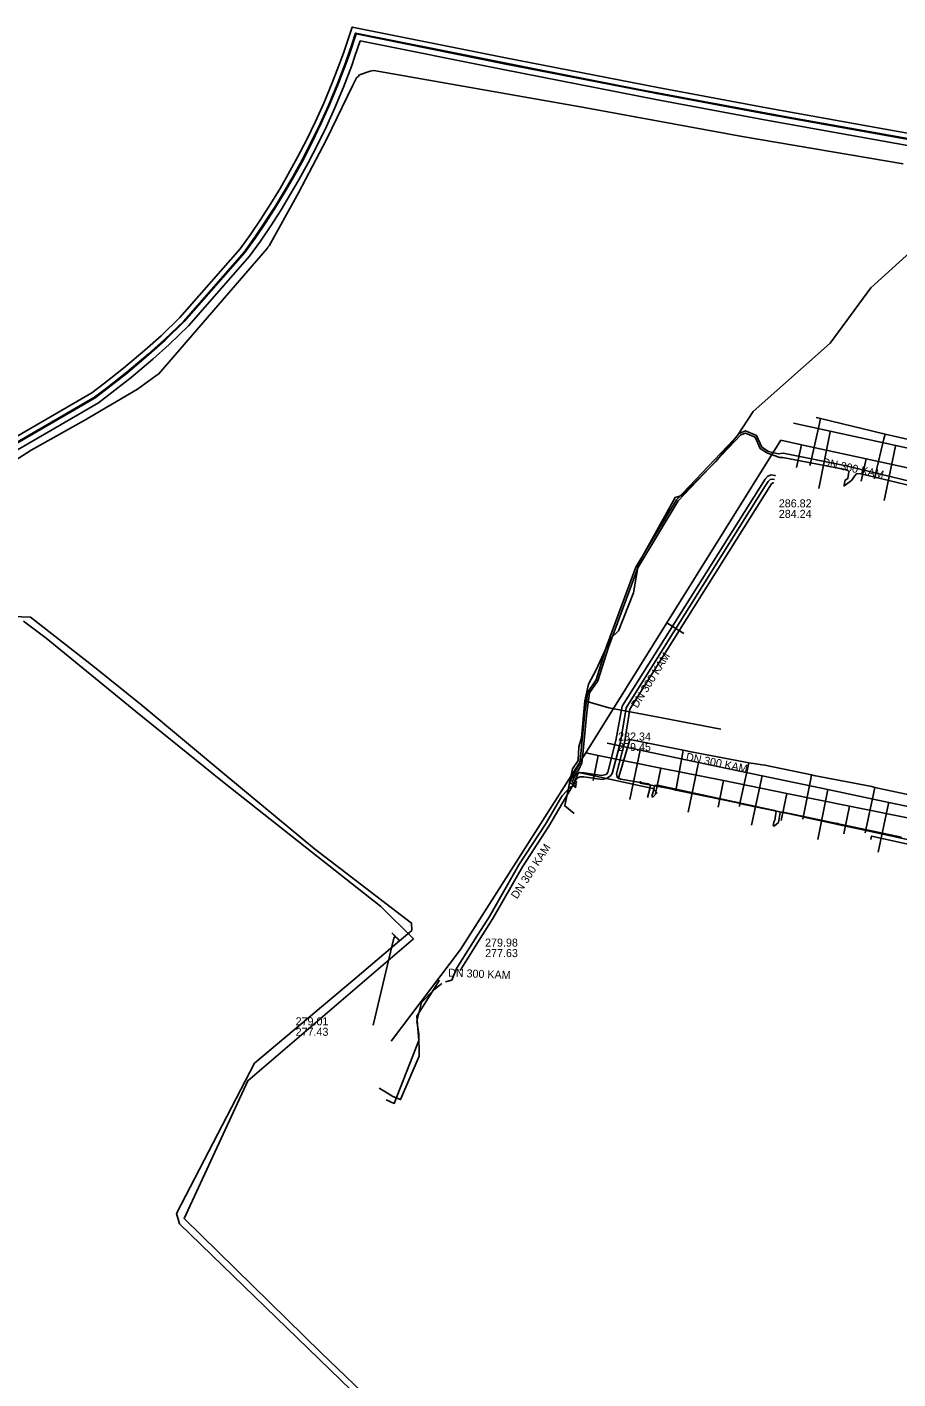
# Model space of a CAD drawing. Extents: x -598233 to -596890, y -1157848 to -1156431.
# Drawn here: x -597318.9 to -597231.9, y -1156858 to -1156722.8 of the extents above; entities that cross this region are included whole.
import ezdxf

# ---------------------------------------------------------------- set-up
doc = ezdxf.new("R2010")
doc.units = 0
for name, color, linetype in [('Vrstva 12', 7, 'Continuous'), ('Vrstva 13', 7, 'Continuous'), ('Vrstva 19', 7, 'Continuous'), ('Vrstva 25', 7, 'Continuous'), ('Vrstva 26', 7, 'Continuous'), ('Vrstva 42', 7, 'Continuous'), ('Vrstva 5', 7, 'Continuous'), ('Vrstva 55', 7, 'Continuous'), ('Vrstva 58', 7, 'Continuous'), ('Vrstva 8', 7, 'Continuous')]:
    doc.layers.add(name, color=color, linetype=linetype)

msp = doc.modelspace()

# ---------------------------------------------------------------- linework, layer by layer
at = {"layer": 'Vrstva 12'}
msp.add_lwpolyline([(-597234.61, -1156804.06), (-597234.54, -1156803.73), (-597231.51, -1156804.39), (-597202.49, -1156810.56)], dxfattribs=at)
at = {"layer": 'Vrstva 13'}
for p, q in [((-597257.65, -1156795.12), (-597258.68, -1156800.08)), ((-597251.82, -1156796.35), (-597252.86, -1156801.33)), ((-597245.48, -1156797.69), (-597246.53, -1156802.62)), ((-597238.9, -1156799.08), (-597239.92, -1156804.08)), ((-597282.25, -1156813.62), (-597282.48, -1156813.4)), ((-597282.12, -1156813.75), (-597282.25, -1156813.62)), ((-597282.12, -1156813.75), (-597281.89, -1156813.97)), ((-597281.69, -1156814.18), (-597281.89, -1156813.97))]:
    msp.add_line(p, q, dxfattribs=at)
for points in [[(-597328.73, -1156771.67), (-597318.51, -1156765.13), (-597313.2, -1156762.16), (-597307.89, -1156759.04), (-597306.04, -1156757.72), (-597305.9, -1156757.62), (-597305.77, -1156757.53), (-597294.93, -1156744.99), (-597294.84, -1156744.85), (-597294.73, -1156744.7), (-597291.79, -1156739.43), (-597288.98, -1156734.09), (-597286.37, -1156728.66), (-597286, -1156727.92), (-597285.84, -1156727.77), (-597285.69, -1156727.63), (-597284.64, -1156727.24), (-597284.46, -1156727.22), (-597284.28, -1156727.2), (-597263.27, -1156730.87), (-597247.46, -1156733.78), (-597231.39, -1156736.52)], [(-597242.34, -1156762.44), (-597238.67, -1156763.25), (-597232.12, -1156764.69), (-597225.66, -1156766.11), (-597219.64, -1156767.44), (-597211.77, -1156769.17), (-597206.62, -1156770.3), (-597200.13, -1156771.73), (-597194.02, -1156773.08), (-597187.41, -1156774.53), (-597180.74, -1156776), (-597175.41, -1156777.17)], [(-597238.67, -1156763.25), (-597238.68, -1156763.3), (-597239.82, -1156768.97)], [(-597232.12, -1156764.69), (-597232.14, -1156764.74), (-597233.28, -1156770.19)], [(-597343.01, -1156780.99), (-597342.89, -1156780.99), (-597335.69, -1156781.22), (-597318.55, -1156781.85), (-597312.16, -1156786.84), (-597307.42, -1156790.67), (-597298.96, -1156797.74), (-597290.18, -1156805), (-597286.05, -1156808.16), (-597280.5, -1156812.42), (-597280.46, -1156813.15), (-597281.69, -1156814.18), (-597286.16, -1156817.99), (-597296.2, -1156826.44), (-597303.98, -1156841.45), (-597303.68, -1156842.47), (-597277.95, -1156867.46), (-597251.84, -1156872.99), (-597228.34, -1156878.54), (-597227.3, -1156877.94), (-597211.22, -1156869.15), (-597195.71, -1156860.7), (-597186.55, -1156856.51)], [(-597181.76, -1156811.13), (-597200.74, -1156807.12), (-597207.19, -1156805.76), (-597213.61, -1156804.41), (-597219.82, -1156803.1), (-597226.76, -1156801.64), (-597232.82, -1156800.36), (-597238.9, -1156799.08), (-597245.48, -1156797.69), (-597251.82, -1156796.35), (-597257.65, -1156795.12), (-597260.62, -1156794.49), (-597260.96, -1156794.42)], [(-597232.82, -1156800.36), (-597232.84, -1156800.45), (-597233.88, -1156805.34)], [(-597282.12, -1156813.75), (-597282.21, -1156813.84), (-597282.28, -1156813.92), (-597284.35, -1156822.64)]]:
    msp.add_lwpolyline(points, dxfattribs=at)
at = {"layer": 'Vrstva 19'}
for points in [[(-597240.7, -1156766.68), (-597240.6, -1156766.3), (-597239.73, -1156762.46), (-597239.63, -1156761.99)], [(-597179.59, -1156774.8), (-597180.46, -1156774.64), (-597182.18, -1156774.29), (-597183.25, -1156774.07), (-597185.39, -1156773.51), (-597188.54, -1156772.81), (-597193.45, -1156771.7), (-597195.12, -1156771.35), (-597199.99, -1156770.31), (-597201.37, -1156770.02), (-597207.42, -1156768.72), (-597214.03, -1156767.29), (-597214.21, -1156767.25), (-597218.45, -1156766.35), (-597220.86, -1156765.93), (-597222.31, -1156765.67), (-597225.99, -1156765.16), (-597226.9, -1156764.97), (-597233.2, -1156763.53), (-597233.31, -1156763.5), (-597239.63, -1156761.99), (-597240.08, -1156761.88)], [(-597234.25, -1156768.01), (-597234.14, -1156767.54), (-597233.32, -1156764.02), (-597233.2, -1156763.53)], [(-597319.25, -1156782.23), (-597316.99, -1156783.95), (-597308.03, -1156791.26), (-597299.37, -1156798.25), (-597290.5, -1156805.3), (-597283.56, -1156810.75), (-597280.31, -1156813.99), (-597296.87, -1156828.19), (-597303.23, -1156841.94), (-597289.53, -1156855.37), (-597278.18, -1156866.27)], [(-597259.86, -1156798.03), (-597259.8, -1156797.8), (-597258.8, -1156794.44), (-597258.69, -1156794.07)], [(-597258.89, -1156794.03), (-597258.69, -1156794.07), (-597253.36, -1156795.14), (-597252.57, -1156795.3), (-597247.3, -1156796.31), (-597246.82, -1156796.39), (-597245.2, -1156796.63), (-597240.53, -1156797.61), (-597240.3, -1156797.66), (-597234.52, -1156798.78), (-597234.23, -1156798.85), (-597227.96, -1156800.21)], [(-597254.11, -1156799.19), (-597254.06, -1156798.96), (-597254.03, -1156798.79), (-597253.44, -1156795.54), (-597253.36, -1156795.14)], [(-597247.75, -1156800.75), (-597247.69, -1156800.46), (-597247.63, -1156800.18), (-597246.91, -1156796.86), (-597246.82, -1156796.39)], [(-597241.42, -1156802.04), (-597241.38, -1156801.85), (-597240.65, -1156798.18), (-597240.53, -1156797.61)], [(-597235.18, -1156803.41), (-597235.11, -1156803.09), (-597234.36, -1156799.5), (-597234.23, -1156798.85)]]:
    msp.add_lwpolyline(points, dxfattribs=at)
at = {"layer": 'Vrstva 25'}
msp.add_lwpolyline([(-597226.77, -1156734.81), (-597245.14, -1156731.52), (-597256, -1156729.49), (-597271.25, -1156726.52), (-597286.03, -1156723.53), (-597286.71, -1156725.55), (-597287.04, -1156726.46), (-597287.87, -1156728.63), (-597288.72, -1156730.69), (-597289.56, -1156732.52), (-597290.43, -1156734.34), (-597291.34, -1156736.14), (-597292.29, -1156737.84), (-597293.12, -1156739.27), (-597294.05, -1156740.81), (-597295.07, -1156742.38), (-597296.09, -1156743.91), (-597297.15, -1156745.39), (-597303.2, -1156752.29), (-597305.11, -1156754.14), (-597306.73, -1156755.59), (-597308.88, -1156757.41), (-597310.79, -1156758.91), (-597312.11, -1156759.9), (-597330.95, -1156770.85)], dxfattribs=at)
at = {"layer": 'Vrstva 26'}
for points in [[(-597331.23, -1156770.32), (-597312.45, -1156759.4), (-597311.16, -1156758.43), (-597309.26, -1156756.94), (-597307.13, -1156755.14), (-597305.52, -1156753.7), (-597303.64, -1156751.88), (-597297.62, -1156745.02), (-597296.58, -1156743.57), (-597295.57, -1156742.05), (-597294.56, -1156740.49), (-597293.64, -1156738.97), (-597292.81, -1156737.54), (-597291.88, -1156735.86), (-597290.97, -1156734.08), (-597290.1, -1156732.27), (-597289.27, -1156730.46), (-597288.42, -1156728.41), (-597287.6, -1156726.25), (-597287.28, -1156725.36), (-597286.43, -1156722.84), (-597271.13, -1156725.93), (-597255.88, -1156728.9), (-597245.04, -1156730.93), (-597227.25, -1156734.12)], [(-597226.3, -1156735.51), (-597245.25, -1156732.11), (-597256.11, -1156730.08), (-597271.36, -1156727.1), (-597285.63, -1156724.23), (-597286.15, -1156725.75), (-597286.48, -1156726.67), (-597287.31, -1156728.85), (-597288.17, -1156730.93), (-597289.01, -1156732.78), (-597289.89, -1156734.61), (-597290.82, -1156736.42), (-597291.77, -1156738.13), (-597292.61, -1156739.58), (-597293.54, -1156741.13), (-597294.57, -1156742.71), (-597295.6, -1156744.25), (-597296.68, -1156745.76), (-597302.77, -1156752.71), (-597304.7, -1156754.57), (-597306.34, -1156756.04), (-597308.5, -1156757.87), (-597310.43, -1156759.38), (-597311.78, -1156760.4), (-597330.68, -1156771.39)]]:
    msp.add_lwpolyline(points, dxfattribs=at)
at = {"layer": 'Vrstva 42'}
for points in [[(-597226.83, -1156734.72), (-597243.23, -1156731.79), (-597251.32, -1156730.29), (-597257.75, -1156729.07), (-597267.87, -1156727.1), (-597277.05, -1156725.26), (-597282.25, -1156724.22), (-597286.09, -1156723.44), (-597286.44, -1156724.49), (-597287.11, -1156726.43), (-597287.94, -1156728.59), (-597288.79, -1156730.67), (-597289.64, -1156732.51), (-597290.5, -1156734.3), (-597291.42, -1156736.11), (-597292.37, -1156737.81), (-597294.12, -1156740.78), (-597296.15, -1156743.86), (-597297.21, -1156745.34), (-597303.25, -1156752.23), (-597305.17, -1156754.08), (-597306.82, -1156755.56), (-597308.93, -1156757.34), (-597310.84, -1156758.84), (-597312.16, -1156759.83), (-597330.99, -1156770.78)], [(-597244.83, -1156765.29), (-597245.51, -1156764.84), (-597246.03, -1156763.68), (-597247.14, -1156763.22), (-597247.7, -1156763.44), (-597254.03, -1156770.1), (-597258.09, -1156776.83), (-597261.02, -1156784.76), (-597262.07, -1156788.1), (-597262.9, -1156789.32), (-597263.18, -1156791.34), (-597263.59, -1156795.51), (-597263.68, -1156796.35), (-597264.01, -1156797.06), (-597264.19, -1156797.22), (-597264.72, -1156798.4), (-597264.37, -1156798.58), (-597264.03, -1156798.76)], [(-597244.94, -1156765.45), (-597245.67, -1156764.98), (-597246.18, -1156763.84), (-597247.14, -1156763.44), (-597247.59, -1156763.61), (-597253.87, -1156770.22), (-597257.91, -1156776.91), (-597260.83, -1156784.82), (-597261.89, -1156788.19), (-597262.71, -1156789.4), (-597262.98, -1156791.36), (-597263.39, -1156795.53), (-597263.49, -1156796.41), (-597263.82, -1156797.14), (-597264.01, -1156797.3), (-597264.13, -1156797.57), (-597264.46, -1156798.31), (-597264.27, -1156798.41), (-597263.99, -1156798.56)], [(-597244.94, -1156765.45), (-597243.7, -1156765.89), (-597243.41, -1156765.86), (-597237.17, -1156767.09), (-597236.9, -1156767.16), (-597236.81, -1156767.29), (-597236.86, -1156767.53), (-597236.93, -1156767.98), (-597237.17, -1156768.13), (-597237.27, -1156768.61), (-597237.29, -1156768.71), (-597236.68, -1156768.29), (-597236.52, -1156768.14), (-597236.26, -1156767.74), (-597236, -1156767.49), (-597235.62, -1156767.5), (-597230.58, -1156768.71)], [(-597230.49, -1156768.32), (-597237.08, -1156766.7), (-597243.39, -1156765.45), (-597243.87, -1156765.51), (-597244.83, -1156765.29)], [(-597275.64, -1156817.16), (-597273.8, -1156814.23), (-597272.37, -1156811.96), (-597269.43, -1156806.8), (-597266.78, -1156802.73), (-597264.47, -1156798.75), (-597264.37, -1156798.58), (-597264.27, -1156798.41), (-597264.17, -1156798.24), (-597264.09, -1156798.11), (-597263.91, -1156797.91), (-597263.64, -1156797.79), (-597263.3, -1156797.8), (-597261.46, -1156798.07), (-597261.04, -1156797.96), (-597260.97, -1156797.94), (-597260.59, -1156797.66), (-597260.46, -1156797.46), (-597259.62, -1156794.32), (-597259.07, -1156790.89), (-597245.14, -1156768.69), (-597244.86, -1156768.27), (-597244.68, -1156768.08), (-597244.41, -1156768.03), (-597244.23, -1156768.08)], [(-597244.15, -1156767.71), (-597244.21, -1156767.69), (-597244.59, -1156767.62), (-597244.91, -1156767.74), (-597245.18, -1156768.03), (-597259.45, -1156790.74), (-597260.09, -1156794.16), (-597260.88, -1156797.32), (-597260.98, -1156797.5), (-597261.1, -1156797.57), (-597261.49, -1156797.66), (-597263.26, -1156797.41), (-597263.63, -1156797.39), (-597263.71, -1156797.38), (-597263.85, -1156797.44), (-597264.13, -1156797.57), (-597264.15, -1156797.58), (-597264.42, -1156797.87)], [(-597256.92, -1156799.88), (-597256.79, -1156799.36), (-597256.7, -1156798.99), (-597256.68, -1156798.91), (-597256.62, -1156798.63), (-597256.86, -1156798.51), (-597259.59, -1156798.04), (-597259.96, -1156797.84), (-597260.02, -1156797.49), (-597259.23, -1156794.41), (-597258.69, -1156791.03), (-597244.54, -1156768.52), (-597244.42, -1156768.4), (-597244.31, -1156768.44)], [(-597256.39, -1156799.82), (-597255.99, -1156799.41), (-597256.31, -1156799.07), (-597256.41, -1156798.97), (-597256.68, -1156798.91), (-597261.04, -1156797.96), (-597263.49, -1156797.42), (-597263.63, -1156797.39), (-597263.81, -1156797.34), (-597263.82, -1156797.38), (-597263.85, -1156797.44), (-597264.2, -1156798.22), (-597264.17, -1156798.24), (-597263.95, -1156798.35)], [(-597265.45, -1156799.71), (-597264.61, -1156798.81), (-597264.47, -1156798.75), (-597264.35, -1156798.71), (-597264.05, -1156798.86)], [(-597231.57, -1156803.82), (-597243.39, -1156801.34), (-597243.67, -1156801.37), (-597243.75, -1156801.75), (-597243.85, -1156802.37), (-597244.23, -1156802.69), (-597244.37, -1156802.7), (-597244.27, -1156802.2), (-597244.22, -1156802.16), (-597244.14, -1156801.67), (-597244.06, -1156801.28), (-597244.24, -1156801.16), (-597255.94, -1156798.63), (-597256.23, -1156798.68), (-597256.31, -1156799.07), (-597256.31, -1156799.08), (-597256.48, -1156799.76), (-597256.39, -1156799.82)], [(-597265.45, -1156799.71), (-597265.63, -1156799.96), (-597267.12, -1156802.53), (-597269.77, -1156806.59), (-597272.72, -1156811.76), (-597274.14, -1156814.01), (-597276, -1156816.97), (-597276.49, -1156818.12), (-597277.1, -1156818.28)], [(-597277.7, -1156818.12), (-597279.96, -1156821.72), (-597279.77, -1156824.15), (-597282.22, -1156830.44), (-597283.05, -1156830.09)], [(-597283.73, -1156828.93), (-597283.17, -1156829.27), (-597282.38, -1156829.76), (-597281.59, -1156830.07), (-597279.73, -1156825.71), (-597279.77, -1156823.54), (-597279.97, -1156822.21), (-597279.49, -1156820.37), (-597278.29, -1156819.12), (-597277.48, -1156818.46)]]:
    msp.add_lwpolyline(points, dxfattribs=at)
at = {"layer": 'Vrstva 5'}
for p, q in [((-597242.03, -1156766.89), (-597241.54, -1156764.61)), ((-597235.58, -1156768.24), (-597235.1, -1156766.01)), ((-597253.3, -1156783.46), (-597254.99, -1156782.4)), ((-597263.1, -1156795.4), (-597275.6, -1156815.05)), ((-597262.37, -1156798.17), (-597261.86, -1156795.65)), ((-597256.12, -1156799.49), (-597255.59, -1156796.92)), ((-597249.88, -1156800.82), (-597249.34, -1156798.18)), ((-597243.57, -1156802.17), (-597243.02, -1156799.46)), ((-597237.31, -1156803.49), (-597236.74, -1156800.73)), ((-597275.6, -1156815.05), (-597282.55, -1156824.21))]:
    msp.add_line(p, q, dxfattribs=at)
for points in [[(-597243.62, -1156764.15), (-597254.99, -1156782.4), (-597263.1, -1156795.4)], [(-597213.25, -1156770.75), (-597216.31, -1156770.09), (-597222.64, -1156768.71), (-597228.67, -1156767.4), (-597235.1, -1156766.01), (-597241.54, -1156764.61), (-597243.62, -1156764.15)], [(-597225.39, -1156803.03), (-597230.46, -1156802.01), (-597236.74, -1156800.73), (-597243.02, -1156799.46), (-597249.34, -1156798.18), (-597255.59, -1156796.92), (-597261.86, -1156795.65), (-597263.1, -1156795.4)]]:
    msp.add_lwpolyline(points, dxfattribs=at)
at = {"layer": 'Vrstva 55'}
msp.add_lwpolyline([(-597229.3, -1156804.42), (-597235.71, -1156803.04), (-597237.93, -1156802.57), (-597237.96, -1156802.43), (-597238.05, -1156802.54), (-597240.98, -1156801.91), (-597241.93, -1156801.67), (-597247.28, -1156800.58), (-597248.07, -1156800.37), (-597253.77, -1156799.19), (-597254.75, -1156798.98), (-597257.67, -1156798.43), (-597257.63, -1156798.22)], dxfattribs=at)
at = {"layer": 'Vrstva 58'}
for points in [[(-597206.92, -1156731.08), (-597208.53, -1156731.6), (-597214.71, -1156735.64), (-597217.58, -1156737.85), (-597223.55, -1156740.66), (-597226.36, -1156742.23), (-597228.97, -1156743.78), (-597234.63, -1156748.91), (-597238.67, -1156754.43), (-597246.37, -1156761.26), (-597247.93, -1156763.67), (-597250.14, -1156766.32), (-597253.5, -1156769.67), (-597254.16, -1156769.87), (-597257.84, -1156776.46), (-597258.33, -1156779.41), (-597259.81, -1156783.2), (-597260.62, -1156783.96), (-597262.04, -1156787.09), (-597262.83, -1156788.54), (-597263.2, -1156790.21)], [(-597263.2, -1156790.21), (-597263.51, -1156793.89), (-597263.78, -1156794.8), (-597263.84, -1156796.16), (-597264.42, -1156797), (-597265.2, -1156800.7), (-597264.27, -1156801.47)], [(-597263.2, -1156790.21), (-597260.79, -1156790.89), (-597255.48, -1156791.91), (-597249.59, -1156793.04)]]:
    msp.add_lwpolyline(points, dxfattribs=at)

# ---------------------------------------------------------------- texts
at = {"layer": 'Vrstva 8'}
for rotation, p in [(347.7281, (-597239.52, -1156766.68)), (58.0406, (-597257.95, -1156790.99)), (348.5545, (-597253.14, -1156796.16)), (57.0093, (-597269.96, -1156810.07)), (357.583, (-597276.86, -1156817.76))]:
    msp.add_text('DN 300 KAM', height=0.8, rotation=rotation, dxfattribs=at).set_placement(p)
for s, p in [('286.82', (-597243.81, -1156770.86)), ('284.24', (-597243.81, -1156771.91)), ('282.34', (-597259.86, -1156794.17)), ('279.45', (-597259.86, -1156795.22)), ('279.98', (-597273.15, -1156814.77)), ('277.63', (-597273.15, -1156815.82)), ('279.01', (-597292.08, -1156822.64)), ('277.43', (-597292.08, -1156823.69))]:
    msp.add_text(s, height=0.8, dxfattribs=at).set_placement(p)

doc.saveas('drawing.dxf')
